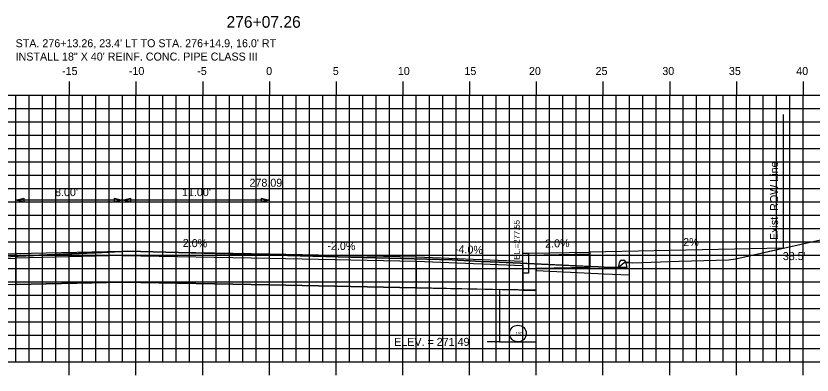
# Model space of a CAD drawing. Extents: x 853785 to 853955, y 366268 to 366378.
# Drawn here: x 853849.4 to 853909.1, y 366306.2 to 366333.2 of the extents above; entities that cross this region are included whole.
import ezdxf

# ---------------------------------------------------------------- set-up
doc = ezdxf.new("R2010")
doc.units = 0
for name, color, linetype in [('ANNOTATION', 7, 'Continuous'), ('D_Curb_Type_1_Rt', 7, 'Continuous'), ('D_Drainage_Text', 7, 'Continuous'), ('D_Roadway_Centerline', 7, 'Continuous'), ('D_Roadway_Centerline_Text', 7, 'Continuous'), ('D_Roadway_Edge_Shoulder', 7, 'Continuous'), ('D_Roadway_FinishedGrade', 7, 'Continuous'), ('D_Roadway_Sidewalks_Paved', 7, 'Continuous'), ('D_Roadway_SubGrade', 7, 'Continuous'), ('D_Text_Standard', 7, 'Continuous'), ('DIMENSIONS', 7, 'Continuous'), ('E_ROW_Line', 7, 'Continuous'), ('H_V ANNOTATION', 7, 'Continuous'), ('JUNK COM EXC', 7, 'Continuous'), ('JUNK FILL', 7, 'Continuous'), ('junk grubnfill', 7, 'Continuous'), ('junk strct exc', 7, 'Continuous'), ('MAJOR', 7, 'Continuous'), ('MINOR', 7, 'Continuous'), ('PDRAIN', 7, 'Continuous'), ('S_Curb_Type_3', 7, 'Continuous'), ('S_Roadway_Centerline', 7, 'Continuous')]:
    doc.layers.add(name, color=color, linetype=linetype)

msp = doc.modelspace()

# ---------------------------------------------------------------- linework, layer by layer
at = {"layer": 'D_Curb_Type_1_Rt'}
msp.add_lwpolyline([(853887.852, 366315.37), (853887.852, 366313.87), (853887.435, 366313.87), (853887.435, 366315.37)], close=True, dxfattribs=at)
at = {"layer": 'D_Roadway_Centerline'}
msp.add_lwpolyline([(853857.435, 366315.531), (853868.435, 366315.326), (853879.435, 366315.106)], dxfattribs=at)
at = {"layer": 'D_Roadway_Edge_Shoulder'}
msp.add_line((853849.435, 366315.344), (853849.435, 366315.011), dxfattribs=at)
for points in [[(853849.435, 366315.344), (853857.435, 366315.531), (853868.435, 366315.326), (853879.435, 366315.106), (853887.431, 366314.787)], [(853843.701, 366315.203), (853849.435, 366315.344)], [(853843.706, 366314.87), (853849.435, 366315.011)]]:
    msp.add_lwpolyline(points, dxfattribs=at)
at = {"layer": 'D_Roadway_FinishedGrade'}
msp.add_line((853906.906, 366315.751), (853892.44, 366315.461), dxfattribs=at)
at = {"layer": 'D_Roadway_Sidewalks_Paved'}
msp.add_lwpolyline([(853887.852, 366315.369), (853892.44, 366315.461), (853892.44, 366315.294), (853887.852, 366315.202)], close=True, dxfattribs=at)
at = {"layer": 'D_Roadway_SubGrade'}
for p, q in [((853857.435, 366315.197), (853849.435, 366315.011)), ((853849.435, 366315.011), (853849.435, 366313.037)), ((853857.435, 366313.197), (853857.435, 366315.197)), ((853895.435, 366313.753), (853895.435, 366314.653)), ((853824.435, 366313.309), (853849.435, 366313.037)), ((853857.435, 366313.197), (853849.435, 366313.037))]:
    msp.add_line(p, q, dxfattribs=at)
for points in [[(853857.435, 366313.197), (853857.435, 366315.197), (853868.435, 366314.993), (853879.435, 366314.773), (853879.435, 366312.773), (853868.435, 366312.993)], [(853879.435, 366314.773), (853887.435, 366314.453), (853887.435, 366312.613), (853879.435, 366312.773)]]:
    msp.add_lwpolyline(points, close=True, dxfattribs=at)
for points in [[(853887.439, 366312.613), (853888.439, 366312.593), (853888.439, 366314.215), (853892.441, 366314.294), (853892.441, 366315.294)], [(853888.439, 366314.075), (853893.047, 366313.858), (853893.496, 366313.837), (853895.435, 366313.753)]]:
    msp.add_lwpolyline(points, dxfattribs=at)
at = {"layer": 'D_Text_Standard'}
msp.add_lwpolyline([(853885.689, 366308.726), (853885.439, 366308.726), (853884.759, 366308.726)], dxfattribs=at)
at = {"layer": 'DIMENSIONS'}
for p, q in [((853849.435, 366315.389), (853849.435, 366319.754)), ((853857.435, 366315.709), (853857.435, 366319.754)), ((853868.435, 366315.526), (853868.435, 366319.754)), ((853857.435, 366319.354), (853849.435, 366319.354)), ((853868.435, 366319.354), (853857.435, 366319.354))]:
    msp.add_line(p, q, dxfattribs=at)
for points in [[(853850.035, 366319.204), (853849.435, 366319.354), (853850.035, 366319.504)], [(853856.835, 366319.504), (853857.435, 366319.354), (853856.835, 366319.204)], [(853858.035, 366319.204), (853857.435, 366319.354), (853858.035, 366319.504)], [(853867.835, 366319.504), (853868.435, 366319.354), (853867.835, 366319.204)]]:
    msp.add_lwpolyline(points, close=True, dxfattribs=at)
at = {"layer": 'E_ROW_Line'}
msp.add_line((853906.959, 366315.764), (853906.959, 366325.764), dxfattribs=at)
at = {"layer": 'JUNK COM EXC'}
msp.add_lwpolyline([(853892.441, 366314.387), (853885.655, 366314.706), (853884.311, 366314.754), (853882.135, 366314.869), (853868.847, 366315.234), (853868.644, 366315.24), (853868.288, 366315.249), (853857.83, 366315.517), (853855.908, 366315.417), (853849.435, 366315.143), (853849.435, 366313.037), (853857.435, 366313.197), (853868.435, 366312.993), (853879.435, 366312.773), (853888.439, 366312.593), (853888.439, 366314.215), (853892.441, 366314.294), (853892.441, 366314.387)], dxfattribs=at)
at = {"layer": 'JUNK FILL'}
msp.add_lwpolyline([(853892.445, 366314.387), (853893.071, 366314.358), (853893.518, 366314.336), (853894.57, 366314.291), (853895.035, 366314.674), (853895.651, 366314.661), (853899.147, 366314.784), (853901.002, 366314.836), (853902.857, 366314.887), (853903.385, 366314.96), (853906.906, 366315.751), (853892.44, 366315.461), (853892.441, 366315.294), (853892.441, 366314.387), (853892.445, 366314.387)], dxfattribs=at)
at = {"layer": 'junk grubnfill'}
msp.add_lwpolyline([(853892.441, 366314.387), (853892.441, 366314.294), (853888.439, 366314.215), (853888.439, 366314.075), (853893.047, 366313.858), (853893.496, 366313.837), (853895.435, 366313.753), (853895.435, 366314.665), (853895.035, 366314.674), (853894.6, 366314.31), (853894.57, 366314.291), (853893.518, 366314.336), (853893.071, 366314.358), (853892.441, 366314.387)], dxfattribs=at)
at = {"layer": 'junk strct exc'}
msp.add_lwpolyline([(853885.689, 366312.648), (853885.689, 366308.726), (853888.439, 366308.726), (853888.439, 366312.593)], close=True, dxfattribs=at)
at = {"layer": 'MAJOR'}
for p, q in [((853853.435, 366328.238), (853853.435, 366327.236)), ((853858.435, 366328.238), (853858.435, 366327.236)), ((853863.435, 366328.238), (853863.435, 366327.236)), ((853868.435, 366328.238), (853868.435, 366327.236)), ((853873.435, 366328.238), (853873.435, 366327.236)), ((853878.435, 366328.238), (853878.435, 366327.236)), ((853883.435, 366328.238), (853883.435, 366327.236)), ((853888.435, 366328.238), (853888.435, 366327.236)), ((853893.435, 366328.238), (853893.435, 366327.236)), ((853898.435, 366328.238), (853898.435, 366327.236)), ((853903.435, 366328.238), (853903.435, 366327.236)), ((853908.435, 366328.238), (853908.435, 366327.236)), ((853798.435, 366327.236), (853938.435, 366327.236)), ((853798.435, 366327.236), (853938.435, 366327.236)), ((853853.435, 366307.236), (853853.435, 366327.236)), ((853858.435, 366307.236), (853858.435, 366327.236)), ((853863.435, 366307.236), (853863.435, 366327.236)), ((853868.435, 366307.236), (853868.435, 366327.236)), ((853873.435, 366307.236), (853873.435, 366327.236)), ((853878.435, 366307.236), (853878.435, 366327.236)), ((853883.435, 366307.236), (853883.435, 366327.236)), ((853888.435, 366307.236), (853888.435, 366327.236)), ((853893.435, 366307.236), (853893.435, 366327.236)), ((853898.435, 366307.236), (853898.435, 366327.236)), ((853903.435, 366307.236), (853903.435, 366327.236)), ((853908.435, 366307.236), (853908.435, 366327.236)), ((853798.435, 366322.236), (853938.435, 366322.236)), ((853798.435, 366317.236), (853938.435, 366317.236)), ((853798.435, 366312.236), (853938.435, 366312.236)), ((853798.435, 366307.236), (853938.435, 366307.236)), ((853798.435, 366307.236), (853938.435, 366307.236)), ((853853.435, 366306.234), (853853.435, 366307.236)), ((853858.435, 366306.234), (853858.435, 366307.236)), ((853863.435, 366306.234), (853863.435, 366307.236)), ((853868.435, 366306.234), (853868.435, 366307.236)), ((853873.435, 366306.234), (853873.435, 366307.236)), ((853878.435, 366306.234), (853878.435, 366307.236)), ((853883.435, 366306.234), (853883.435, 366307.236)), ((853888.435, 366306.234), (853888.435, 366307.236)), ((853893.435, 366306.234), (853893.435, 366307.236)), ((853898.435, 366306.234), (853898.435, 366307.236)), ((853903.435, 366306.234), (853903.435, 366307.236)), ((853908.435, 366306.234), (853908.435, 366307.236))]:
    msp.add_line(p, q, dxfattribs=at)
at = {"layer": 'MINOR'}
for p, q in [((853849.435, 366307.236), (853849.435, 366327.236)), ((853850.435, 366307.236), (853850.435, 366327.236)), ((853851.435, 366307.236), (853851.435, 366327.236)), ((853852.435, 366307.236), (853852.435, 366327.236)), ((853854.435, 366307.236), (853854.435, 366327.236)), ((853855.435, 366307.236), (853855.435, 366327.236)), ((853856.435, 366307.236), (853856.435, 366327.236)), ((853857.435, 366307.236), (853857.435, 366327.236)), ((853859.435, 366307.236), (853859.435, 366327.236)), ((853860.435, 366307.236), (853860.435, 366327.236)), ((853861.435, 366307.236), (853861.435, 366327.236)), ((853862.435, 366307.236), (853862.435, 366327.236)), ((853864.435, 366307.236), (853864.435, 366327.236)), ((853865.435, 366307.236), (853865.435, 366327.236)), ((853866.435, 366307.236), (853866.435, 366327.236)), ((853867.435, 366307.236), (853867.435, 366327.236)), ((853869.435, 366307.236), (853869.435, 366327.236)), ((853870.435, 366307.236), (853870.435, 366327.236)), ((853871.435, 366307.236), (853871.435, 366327.236)), ((853872.435, 366307.236), (853872.435, 366327.236)), ((853874.435, 366307.236), (853874.435, 366327.236)), ((853875.435, 366307.236), (853875.435, 366327.236)), ((853876.435, 366307.236), (853876.435, 366327.236)), ((853877.435, 366307.236), (853877.435, 366327.236)), ((853879.435, 366307.236), (853879.435, 366327.236)), ((853880.435, 366307.236), (853880.435, 366327.236)), ((853881.435, 366307.236), (853881.435, 366327.236)), ((853882.435, 366307.236), (853882.435, 366327.236)), ((853884.435, 366307.236), (853884.435, 366327.236)), ((853885.435, 366307.236), (853885.435, 366327.236)), ((853886.435, 366307.236), (853886.435, 366327.236)), ((853887.435, 366307.236), (853887.435, 366327.236)), ((853889.435, 366307.236), (853889.435, 366327.236)), ((853890.435, 366307.236), (853890.435, 366327.236)), ((853891.435, 366307.236), (853891.435, 366327.236)), ((853892.435, 366307.236), (853892.435, 366327.236)), ((853894.435, 366307.236), (853894.435, 366327.236)), ((853895.435, 366307.236), (853895.435, 366327.236)), ((853896.435, 366307.236), (853896.435, 366327.236)), ((853897.435, 366307.236), (853897.435, 366327.236)), ((853899.435, 366307.236), (853899.435, 366327.236)), ((853900.435, 366307.236), (853900.435, 366327.236)), ((853901.435, 366307.236), (853901.435, 366327.236)), ((853902.435, 366307.236), (853902.435, 366327.236)), ((853904.435, 366307.236), (853904.435, 366327.236)), ((853905.435, 366307.236), (853905.435, 366327.236)), ((853906.435, 366307.236), (853906.435, 366327.236)), ((853907.435, 366307.236), (853907.435, 366327.236)), ((853798.435, 366326.236), (853938.435, 366326.236)), ((853798.435, 366325.236), (853938.435, 366325.236)), ((853798.435, 366324.236), (853938.435, 366324.236)), ((853798.435, 366323.236), (853938.435, 366323.236)), ((853798.435, 366321.236), (853938.435, 366321.236)), ((853798.435, 366320.236), (853938.435, 366320.236)), ((853798.435, 366319.236), (853938.435, 366319.236)), ((853798.435, 366318.236), (853938.435, 366318.236)), ((853798.435, 366316.236), (853938.435, 366316.236)), ((853798.435, 366315.236), (853938.435, 366315.236)), ((853798.435, 366314.236), (853938.435, 366314.236)), ((853798.435, 366313.236), (853938.435, 366313.236)), ((853798.435, 366311.236), (853938.435, 366311.236)), ((853798.435, 366310.236), (853938.435, 366310.236)), ((853798.435, 366309.236), (853938.435, 366309.236)), ((853798.435, 366308.236), (853938.435, 366308.236))]:
    msp.add_line(p, q, dxfattribs=at)
at = {"layer": 'PDRAIN'}
msp.add_lwpolyline([(853885.689, 366312.648), (853885.689, 366308.726), (853888.439, 366308.726), (853888.439, 366312.593)], dxfattribs=at)
msp.add_circle((853887.064, 366309.351), 0.625, dxfattribs=at)
at = {"layer": 'S_Curb_Type_3'}
for points in [[(853895.123, 366314.755), (853895.225, 366314.31), (853894.6, 366314.31), (853894.703, 366314.755)], [(853894.825, 366314.852), (853895.001, 366314.852)]]:
    msp.add_lwpolyline(points, dxfattribs=at)
for centre, start, end in [((853894.825, 366314.727), 90, 167.00538), ((853895.001, 366314.727), 12.99462, 90)]:
    msp.add_arc(centre, 0.125, start, end, dxfattribs=at)
at = {"layer": 'S_Roadway_Centerline'}
msp.add_lwpolyline([(853838.725, 366314.689), (853855.908, 366315.417), (853857.83, 366315.517), (853868.288, 366315.249), (853868.644, 366315.24), (853868.847, 366315.234), (853882.135, 366314.869), (853884.311, 366314.754), (853885.655, 366314.706), (853893.071, 366314.358), (853893.518, 366314.336), (853894.57, 366314.291), (853894.6, 366314.31), (853895.035, 366314.674), (853895.651, 366314.661), (853899.147, 366314.784), (853902.857, 366314.887), (853903.385, 366314.96), (853909.745, 366316.389), (853910.623, 366316.347), (853919.12, 366316.227), (853919.151, 366316.863), (853919.384, 366318.089)], dxfattribs=at)

# ---------------------------------------------------------------- texts
at = {"layer": 'ANNOTATION'}
for s, rotation, p in [('2.0%', 358.93445, (853861.937, 366315.847)), ('-2.0%', 358.85424, (853872.778, 366315.639)), ('2.0%', 1.14881, (853889.108, 366315.795)), ('2%', 1.14841, (853899.457, 366315.902)), ('-4.0%', 357.70927, (853882.329, 366315.392))]:
    msp.add_text(s, height=0.6, rotation=rotation, dxfattribs=at).set_placement(p)
at = {"layer": 'D_Drainage_Text'}
for s, p in [("STA. 276+13.26, 23.4' LT TO STA. 276+14.9, 16.0' RT", (853849.412, 366330.818)), ('INSTALL 18" X 40\' REINF. CONC. PIPE CLASS III', (853849.412, 366329.818))]:
    msp.add_text(s, height=0.6, dxfattribs=at).set_placement(p)
at = {"layer": 'D_Roadway_Centerline_Text'}
msp.add_text('278.09', height=0.6, dxfattribs=at).set_placement((853866.942, 366320.358))
at = {"layer": 'D_Text_Standard'}
msp.add_text(' EL.=277.55', height=0.4335, rotation=90, dxfattribs=at).set_placement((853887.19, 366314.717))
for s, p in [("38.5'", (853906.914, 366314.857)), ('ELEV. = 271.49', (853877.787, 366308.426))]:
    msp.add_text(s, height=0.6, dxfattribs=at).set_placement(p)
at = {"layer": 'DIMENSIONS'}
for s, p in [("8.00'", (853852.368, 366319.654)), ("11.00'", (853861.884, 366319.654))]:
    msp.add_text(s, height=0.6, dxfattribs=at).set_placement(p)
at = {"layer": 'E_ROW_Line'}
msp.add_text('Exist. ROW Line', height=0.6, rotation=90, dxfattribs=at).set_placement((853906.559, 366316.364))
at = {"layer": 'H_V ANNOTATION'}
for s, height, p in [('276+07.26', 0.875, (853865.22, 366332.28)), ('-15', 0.6, (853852.892, 366328.736)), ('-10', 0.6, (853857.9, 366328.736)), ('-5', 0.6, (853863.026, 366328.736)), ('0', 0.6, (853868.194, 366328.736)), ('5', 0.6, (853873.186, 366328.736)), ('10', 0.6, (853878.061, 366328.736)), ('15', 0.6, (853883.053, 366328.736)), ('20', 0.6, (853887.889, 366328.736)), ('25', 0.6, (853892.881, 366328.736)), ('30', 0.6, (853897.884, 366328.736)), ('35', 0.6, (853902.876, 366328.736)), ('40', 0.6, (853907.921, 366328.736))]:
    msp.add_text(s, height=height, dxfattribs=at).set_placement(p)
at = {"layer": 'PDRAIN'}
msp.add_text('15"', height=0.25, dxfattribs=at).set_placement((853886.877, 366309.226))
at = {"layer": 'S_Roadway_Centerline'}
for s, p in [('C', (853868.639, 366315.24)), ('L', (853868.644, 366315.233))]:
    msp.add_text(s, height=0.0146, dxfattribs=at).set_placement(p)

doc.saveas('drawing.dxf')
